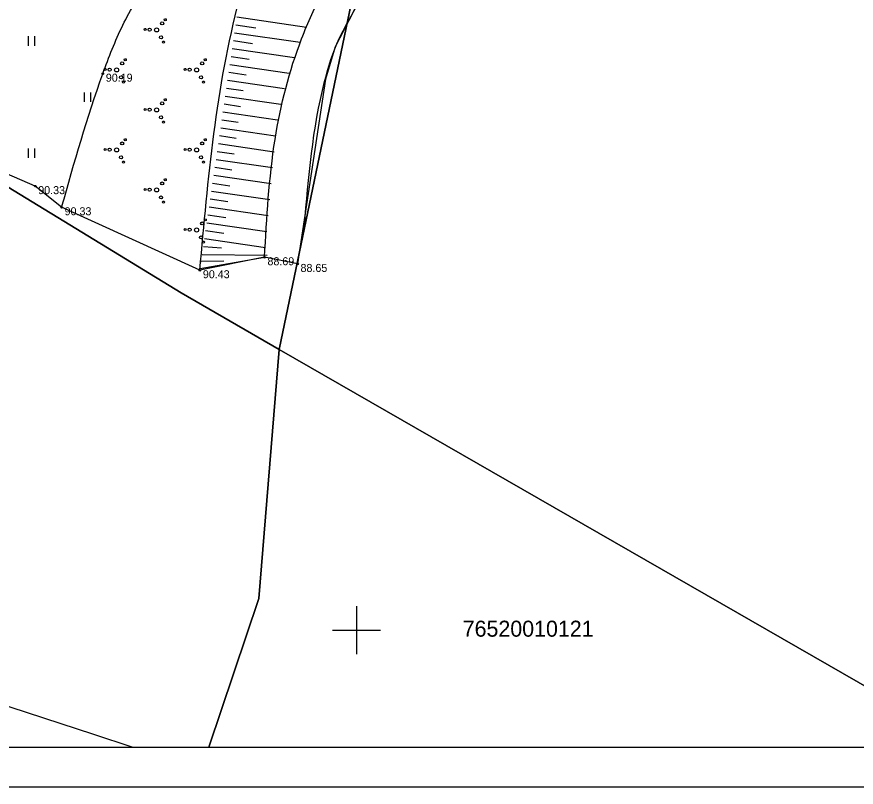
# Model space of a CAD drawing. Extents: x 635228 to 635525, y 248590 to 248800.
# Drawn here: x 635378.8 to 635431.2, y 248590.2 to 248638.3 of the extents above; entities that cross this region are included whole.
import ezdxf

# ---------------------------------------------------------------- set-up
doc = ezdxf.new("R2010")
doc.units = 0
for name, color, linetype in [('GEOD_ELEM_####_####_#', 7, 'Continuous'), ('HIDG_GRAV_####_####_#', 7, 'Continuous'), ('RAMI_PLAN_####_TKST_#', 7, 'Continuous'), ('RAMI_UZMR_####_####_#', 7, 'Continuous'), ('RELJ_AATZ_####_TKST_#', 7, 'Continuous'), ('RELJ_ELEM_####_####_#', 7, 'Continuous'), ('RELJ_NOGA_####_####_#', 7, 'Continuous'), ('ROBZ_UZMR_####_####_#', 7, 'Continuous'), ('ROBZ_UZMR_####_TKST_#', 7, 'Continuous'), ('TERT_ELEM_####_####_#', 7, 'Continuous'), ('TERT_KONT_####_####_#', 7, 'Continuous')]:
    doc.layers.add(name, color=color, linetype=linetype)

msp = doc.modelspace()

# ---------------------------------------------------------------- linework, layer by layer
at = {"layer": 'GEOD_ELEM_####_####_#'}
for p, q in [((635400, 248601.5), (635400, 248600)), ((635398.5, 248600), (635400, 248600)), ((635400, 248600), (635400, 248598.5)), ((635400, 248600), (635401.5, 248600))]:
    msp.add_line(p, q, dxfattribs=at)
at = {"layer": 'HIDG_GRAV_####_####_#'}
for points in [[(635394.244, 248623.295), (635394.9074355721, 248630.6631552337), (635396.5650242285, 248636.944974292), (635397.8888882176, 248639.97580624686), (635399.2686043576, 248642.98780740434), (635400.0423829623, 248644.69884236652), (635400.835233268, 248646.3905777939), (635402.4795660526, 248649.72803076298), (635404.20443685, 248653.0239277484), (635406.0126797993, 248656.30203018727), (635407.0670223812, 248658.14081276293), (635408.1930324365, 248659.92698593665), (635409.4621962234, 248661.60192368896), (635410.172800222, 248662.37935865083), (635410.946, 248663.10700000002), (635413.0008032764, 248664.6744257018), (635415.1640977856, 248666.05372522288), (635417.3478434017, 248667.38916213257), (635419.464, 248668.825), (635422.2083511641, 248670.85354035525), (635424.965867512, 248672.86854694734), (635430.4558647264, 248676.93578902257), (635435.8049295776, 248681.1823865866), (635438.3862804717, 248683.4215875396), (635439.6466024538, 248684.57867623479), (635440.8840000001, 248685.76400000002), (635443.6087249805, 248688.6747140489), (635446.1599310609, 248691.73220612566), (635448.6719216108, 248694.81834513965), (635451.279, 248697.815), (635453.9336502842, 248700.48189136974), (635456.6811388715, 248703.07136968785), (635459.3523080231, 248705.7266631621), (635461.7780000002, 248708.59100000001), (635461.778, 248708.59100000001)], [(635396.7397638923, 248625.2320466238), (635397.9986579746, 248634.27312358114), (635398.9188026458, 248636.96227546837), (635399.5920874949, 248638.24717771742), (635399.9292604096, 248638.88899780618), (635400.2466831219, 248639.53584001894), (635401.591165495, 248642.41958219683), (635402.9524948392, 248645.2868638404), (635405.8217854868, 248650.96088254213), (635407.5583128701, 248653.91205967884), (635409.4799859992, 248656.7354955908), (635411.5283407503, 248659.48290512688), (635413.6449129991, 248662.20600313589), (635414.8182615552, 248663.6538935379), (635415.4704678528, 248664.3057478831), (635416.2076616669, 248664.85985159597), (635417.1601741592, 248665.41138033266), (635418.1313630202, 248665.91742947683), (635419.1067857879, 248666.41122678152), (635420.072, 248666.926), (635421.5645353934, 248667.7418115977), (635423.0692260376, 248668.5354410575), (635426.0762392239, 248670.12612318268), (635429.0153718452, 248671.8379856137), (635430.4352117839, 248672.78309045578), (635431.128452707, 248673.2855892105), (635431.8089561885, 248673.81096758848), (635433.1953696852, 248675.0040709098), (635434.526751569, 248676.2563297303), (635437.0226234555, 248678.92292892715), (635441.762, 248684.467), (635443.1273679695, 248686.0473501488), (635444.4678763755, 248687.6485508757), (635447.1219662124, 248690.87245996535), (635449.819572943, 248694.05663907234), (635451.2144774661, 248695.60817732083), (635452.6560000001, 248697.119), (635458.0231966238, 248702.2419696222), (635463.584, 248707.15000000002)]]:
    msp.add_spline(points, degree=3, dxfattribs=at)
at = {"layer": 'RAMI_PLAN_####_TKST_#'}
for points in [[(635227.8373132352, 248590.17647954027), (635227.8373132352, 248800.17647954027), (635524.8373132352, 248800.17647954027), (635524.8373132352, 248590.17647954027)], [(635237.8373132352, 248797.67647954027), (635237.8373132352, 248592.67647954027), (635522.3373132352, 248592.67647954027), (635522.3373132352, 248797.67647954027)]]:
    msp.add_lwpolyline(points, close=True, dxfattribs=at)
at = {"layer": 'RAMI_UZMR_####_####_#'}
msp.add_lwpolyline([(635426.003, 248728.15499999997), (635436.69, 248722.584), (635450.108, 248715.45700000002), (635458.287, 248711.34600000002), (635461.7780000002, 248708.59100000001), (635463.584, 248707.15000000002), (635452.6560000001, 248697.119), (635441.762, 248684.467), (635435.9528772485, 248677.73413872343), (635432.018527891, 248673.97985762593), (635429.363741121, 248672.06248825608), (635427.0556775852, 248670.66460585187), (635420.072, 248666.926), (635415.05332695, 248664.00973325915), (635408.095218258, 248654.65947737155), (635398.6701763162, 248636.43948679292), (635398.046283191, 248634.41686083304), (635396.3166782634, 248622.87374513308), (635394.244, 248623.295), (635390.206, 248622.483), (635381.566, 248626.41900000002), (635379.918, 248627.738), (635364.657, 248634.36500000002)], dxfattribs=at)
at = {"layer": 'RELJ_ELEM_####_####_#'}
for centre in [(635384.141, 248634.765), (635379.918, 248627.738), (635381.566, 248626.41900000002), (635394.244, 248623.295), (635396.309591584, 248622.87746243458), (635390.206, 248622.483)]:
    msp.add_circle(centre, 0.05, dxfattribs=at)
at = {"layer": 'RELJ_NOGA_####_####_#'}
for p, q in [((635392.5155768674, 248638.31543047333), (635396.868432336, 248637.6804518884)), ((635392.4434025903, 248637.82066702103), (635393.7114644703, 248637.6356868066)), ((635392.3712283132, 248637.32590356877), (635396.478144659, 248636.72680168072)), ((635392.299054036, 248636.83114011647), (635393.4972772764, 248636.6563477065)), ((635392.2268797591, 248636.33637666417), (635396.1155335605, 248635.76911411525)), ((635392.154705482, 248635.84161321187), (635393.2922735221, 248635.67566895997)), ((635392.0825312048, 248635.3468497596), (635395.7869034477, 248634.8064695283)), ((635392.0103569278, 248634.8520863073), (635393.0984267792, 248634.69336266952)), ((635391.9381826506, 248634.357322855), (635395.498235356, 248633.83799542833)), ((635391.7938340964, 248633.3677959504), (635395.2552614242, 248632.86285563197)), ((635391.8660083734, 248633.8625594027), (635392.9173902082, 248633.7091876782)), ((635391.7216598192, 248632.87303249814), (635392.7509950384, 248632.72287685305)), ((635391.6494855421, 248632.37826904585), (635395.0638883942, 248631.8801884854)), ((635391.577311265, 248631.88350559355), (635392.6008866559, 248631.73419017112)), ((635391.5051369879, 248631.38874214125), (635394.9294934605, 248630.88920958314)), ((635391.4329627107, 248630.89397868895), (635392.4679453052, 248630.74299922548)), ((635391.3607884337, 248630.39921523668), (635394.8379975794, 248629.89197272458)), ((635391.2886141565, 248629.9044517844), (635392.3399570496, 248629.75108574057)), ((635391.2164398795, 248629.4096883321), (635394.7481833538, 248628.8944905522)), ((635391.1442656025, 248628.9149248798), (635392.211968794, 248628.75917225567)), ((635391.0720913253, 248628.42016142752), (635394.6583691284, 248627.89700837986)), ((635390.9999170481, 248627.92539797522), (635392.0839805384, 248627.76725877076)), ((635390.9277427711, 248627.43063452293), (635394.5685549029, 248626.8995262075)), ((635390.855568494, 248626.93587107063), (635391.9559922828, 248626.77534528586)), ((635390.7833942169, 248626.44110761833), (635394.4787406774, 248625.90204403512)), ((635390.7112199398, 248625.94634416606), (635391.8280040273, 248625.7834318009)), ((635390.5668713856, 248624.95681726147), (635391.7000157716, 248624.791518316)), ((635390.6390456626, 248625.45158071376), (635394.3889264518, 248624.90456186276)), ((635390.4946971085, 248624.46205380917), (635394.2991122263, 248623.90707969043)), ((635390.4225228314, 248623.9672903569), (635391.5532261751, 248623.88850327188)), ((635390.3503485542, 248623.4725269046), (635390.3513380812, 248623.472382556)), ((635390.3505103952, 248623.47363634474), (635394.4025253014, 248623.42991573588)), ((635390.2213141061, 248622.58798006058), (635394.244, 248623.295)), ((635390.2781742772, 248622.9777634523), (635390.2784711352, 248622.97772014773)), ((635390.2887885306, 248623.05052545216), (635391.7100063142, 248623.07360416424)), ((635390.206, 248622.483), (635390.206989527, 248622.48285565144))]:
    msp.add_line(p, q, dxfattribs=at)
msp.add_spline([(635390.206, 248622.483), (635392.6761559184, 248639.41621940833), (635395.6724652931, 248647.2597307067), (635397.9131924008, 248650.95381667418), (635399.048256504, 248652.79837067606), (635400.128, 248654.662), (635400.9493075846, 248656.2558432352), (635403.3016292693, 248661.16811378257), (635405.1862207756, 248664.14373210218), (635407.706, 248666.499), (635412.1610828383, 248669.3503906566), (635416.627, 248672.168), (635424.6828055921, 248677.31078055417), (635432.728, 248682.47600000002), (635436.7060689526, 248685.70428438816), (635438.5008534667, 248687.5575466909), (635440.2150000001, 248689.48700000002), (635442.5291182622, 248692.3528262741), (635444.7219287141, 248695.30565037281), (635446.9190248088, 248698.24939928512), (635449.246, 248701.08800000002), (635451.3600052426, 248703.48451832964), (635453.4937434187, 248705.86484004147), (635457.9500000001, 248710.44), (635458.6576193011, 248711.10744185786)], degree=3, dxfattribs=at)
at = {"layer": 'ROBZ_UZMR_####_####_#'}
msp.add_lwpolyline([(635325.5420000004, 248659.74000000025), (635329.6529999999, 248676.3660000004), (635327.79, 248676.82799999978), (635337.4600999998, 248688.65990000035), (635343.3430000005, 248703.1199999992), (635360.483, 248762.61500000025), (635458.6069999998, 248711.13399999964), (635465.4589999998, 248707.53900000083), (635439.4570000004, 248681.03800000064), (635424.5429999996, 248670.01400000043), (635420.9790000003, 248667.37900000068), (635407.0700000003, 248653.17999999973), (635400.0669999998, 248641.1490000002), (635395.1619999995, 248617.53900000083), (635389.0310000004, 248621.06200000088), (635375.858, 248629.11500000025)], close=True, dxfattribs=at)
for points in [[(635432.3373132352, 248596.18186087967), (635395.1619999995, 248617.53900000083), (635400.0669999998, 248641.1490000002), (635407.0700000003, 248653.17999999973), (635420.9790000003, 248667.37900000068), (635424.5429999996, 248670.01400000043), (635430.9589999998, 248667.77300000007), (635522.3373132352, 248635.85405923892)], [(635385.967280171, 248592.67647954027), (635383.5700000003, 248593.46000000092), (635239.4919999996, 248640.54499999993), (635247.6310000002, 248661.6490000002), (635302.8550000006, 248630.5580000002), (635325.5420000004, 248659.74000000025), (635375.858, 248629.11500000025), (635389.0310000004, 248621.06200000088), (635395.1619999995, 248617.53900000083), (635393.8799999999, 248601.96000000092), (635390.7661109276, 248592.67647954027)], [(635390.7661109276, 248592.6764795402), (635393.8799999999, 248601.96000000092), (635395.1619999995, 248617.53900000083), (635432.3373132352, 248596.18186087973)]]:
    msp.add_lwpolyline(points, dxfattribs=at)
at = {"layer": 'TERT_ELEM_####_####_#'}
for p, q in [((635379.5, 248636.5), (635379.5, 248637.1)), ((635379.9, 248636.5), (635379.9, 248637.1)), ((635383, 248633), (635383, 248633.6)), ((635383.4, 248633), (635383.4, 248633.6)), ((635379.5, 248629.5), (635379.5, 248630.1)), ((635379.9, 248629.5), (635379.9, 248630.1))]:
    msp.add_line(p, q, dxfattribs=at)
for centre, radius in [((635388.044, 248638.13935999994), 0.06400000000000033), ((635386.7816, 248637.53423999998), 0.06400000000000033), ((635387.06608, 248637.52079999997), 0.09600000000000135), ((635387.5, 248637.5), 0.12800000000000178), ((635387.8475200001, 248637.90767999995), 0.09600000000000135), ((635387.77648, 248637.03311999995), 0.09600000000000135), ((635387.93392, 248636.74383999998), 0.06400000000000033), ((635385.3475200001, 248635.40767999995), 0.09600000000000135), ((635385.544, 248635.63935999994), 0.06400000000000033), ((635390.3475200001, 248635.40767999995), 0.09600000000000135), ((635390.544, 248635.63935999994), 0.06400000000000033), ((635384.2816, 248635.03423999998), 0.06400000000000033), ((635384.56608, 248635.02079999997), 0.09600000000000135), ((635385, 248635), 0.12800000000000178), ((635389.2816, 248635.03423999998), 0.06400000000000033), ((635389.56608, 248635.02079999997), 0.09600000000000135), ((635390, 248635), 0.12800000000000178), ((635385.27648, 248634.53311999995), 0.09600000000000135), ((635390.27648, 248634.53311999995), 0.09600000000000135), ((635385.43392, 248634.24383999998), 0.06400000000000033), ((635390.43392, 248634.24383999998), 0.06400000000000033), ((635387.8475200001, 248632.90767999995), 0.09600000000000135), ((635388.044, 248633.13935999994), 0.06400000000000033), ((635386.7816, 248632.53423999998), 0.06400000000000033), ((635387.06608, 248632.52079999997), 0.09600000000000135), ((635387.5, 248632.5), 0.12800000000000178), ((635387.77648, 248632.03311999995), 0.09600000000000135), ((635387.93392, 248631.74383999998), 0.06400000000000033), ((635385.3475200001, 248630.40767999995), 0.09600000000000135), ((635385.544, 248630.63935999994), 0.06400000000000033), ((635390.3475200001, 248630.40767999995), 0.09600000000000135), ((635390.544, 248630.63935999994), 0.06400000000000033), ((635384.2816, 248630.03423999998), 0.06400000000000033), ((635384.56608, 248630.02079999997), 0.09600000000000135), ((635385, 248630), 0.12800000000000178), ((635389.2816, 248630.03423999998), 0.06400000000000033), ((635389.56608, 248630.02079999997), 0.09600000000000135), ((635390, 248630), 0.12800000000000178), ((635385.27648, 248629.53311999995), 0.09600000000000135), ((635385.43392, 248629.24383999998), 0.06400000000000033), ((635390.27648, 248629.53311999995), 0.09600000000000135), ((635390.43392, 248629.24383999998), 0.06400000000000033), ((635388.044, 248628.13935999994), 0.06400000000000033), ((635386.7816, 248627.53423999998), 0.06400000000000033), ((635387.06608, 248627.52079999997), 0.09600000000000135), ((635387.5, 248627.5), 0.12800000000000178), ((635387.8475200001, 248627.90767999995), 0.09600000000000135), ((635387.77648, 248627.03311999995), 0.09600000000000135), ((635387.93392, 248626.74383999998), 0.06400000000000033), ((635390.3475200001, 248625.40767999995), 0.09600000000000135), ((635390.544, 248625.63935999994), 0.06400000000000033), ((635389.2816, 248625.03423999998), 0.06400000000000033), ((635389.56608, 248625.02079999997), 0.09600000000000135), ((635390, 248625), 0.12800000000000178), ((635390.27648, 248624.53311999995), 0.09600000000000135), ((635390.43392, 248624.24383999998), 0.06400000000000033)]:
    msp.add_circle(centre, radius, dxfattribs=at)
at = {"layer": 'TERT_KONT_####_####_#'}
msp.add_spline([(635381.566, 248626.41900000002), (635384.141, 248634.765), (635385.389202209, 248637.7914590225), (635387.0292419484, 248640.6516206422), (635388.8146607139, 248643.4497219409), (635389.6848689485, 248644.8580740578), (635390.4990000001, 248646.29), (635392.0226550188, 248649.21918285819), (635393.5071185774, 248652.1702394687), (635395.0017728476, 248655.12192634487), (635396.556, 248658.053), (635399.9011134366, 248663.08488427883), (635403.9259848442, 248667.61643358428), (635408.395257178, 248671.78623589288), (635410.7229946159, 248673.7787906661), (635413.0735733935, 248675.7328791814), (635414.4692599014, 248676.62068389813), (635415.9938205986, 248677.30794837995), (635417.5018643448, 248678.0054584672), (635418.848, 248678.924), (635420.219040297, 248680.28079949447), (635421.4913245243, 248681.74225536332), (635423.8682567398, 248684.84208090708), (635426.2360605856, 248687.94936599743), (635428.1606833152, 248690.11983046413), (635428.8520000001, 248690.79), (635429.5317929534, 248691.3720486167), (635430.2428233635, 248691.92597447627), (635430.954192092, 248692.47941309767), (635431.635, 248693.06), (635432.7520114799, 248694.18745503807), (635433.7815998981, 248695.39485218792), (635435.7079899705, 248697.94525714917), (635437.6731350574, 248700.50278353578), (635438.7511672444, 248701.71908246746), (635439.936, 248702.85900000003), (635442.1191491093, 248704.47891720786), (635444.4652000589, 248705.76616705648), (635446.9243060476, 248706.83607415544), (635448.1806775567, 248707.32556311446), (635449.4466202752, 248707.80396311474), (635450.5789798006, 248708.1275799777), (635451.7602437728, 248708.30057270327), (635452.9245409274, 248708.35276985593), (635454.0060000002, 248708.314), (635454.3355621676, 248708.1390314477), (635454.6423695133, 248707.79518323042), (635454.9454921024, 248707.47799339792), (635455.2640000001, 248707.383), (635455.8819855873, 248707.57371461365), (635456.5298319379, 248707.8540188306), (635457.157262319, 248708.21606363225), (635457.714, 248708.652), (635459.5420464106, 248710.35555231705)], degree=3, dxfattribs=at)

# ---------------------------------------------------------------- texts
at = {"layer": 'RELJ_AATZ_####_TKST_#'}
for s, p in [(' 90.19', (635384.141, 248634.265)), (' 90.33', (635379.918, 248627.238)), (' 90.33', (635381.566, 248625.91900000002)), (' 88.69', (635394.244, 248622.795)), (' 88.65', (635396.309591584, 248622.37746243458)), (' 90.43', (635390.206, 248621.983))]:
    msp.add_text(s, height=0.5, dxfattribs=at).set_placement(p)
at = {"layer": 'ROBZ_UZMR_####_TKST_#'}
msp.add_text('76520010121', height=1, dxfattribs=at).set_placement((635406.6315877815, 248599.5824587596))

doc.saveas('drawing.dxf')
